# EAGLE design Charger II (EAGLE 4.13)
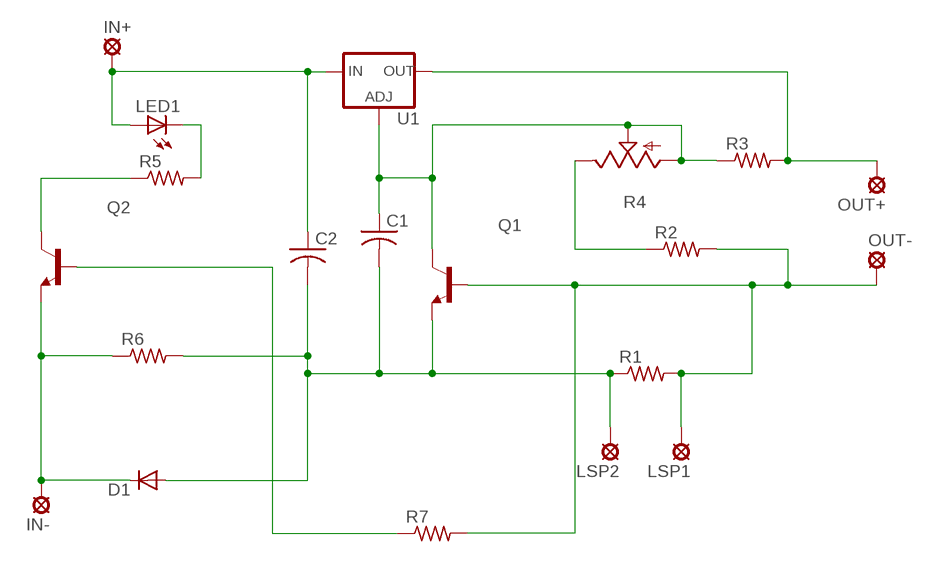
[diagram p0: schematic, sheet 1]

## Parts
C1  C-US050-024X044  [C050-024X044]
C2  C-US050-024X044  [C050-024X044]
D1  DIODE-C1702-05  [C1702-05]
IN+  SE14  [SE14]
IN-  SE14  [SE14]
LED1  LED3MM  [LED3MM]
LSP1  MCS08  [MCS08]
LSP2  MCS08  [MCS08]
OUT+  SE14  [SE14]
OUT-  SE14  [SE14]
Q1  2N3904  [TO92]
Q2  2N3904  [TO92]
R1  R-US_0207/2V  [0207/2V]
R2  R-US_0204/2V  [0204V]
R3  R-US_0204/2V  [0204V]
R4  TRIM_US-PTSPIN  [PT-SPIN]
R5  R-US_0207/2V  [0207/2V]
R6  R-US_0207/2V  [0207/2V]
R7  R-US_0309/V  [0309V]
U1  LM317TS  [317TS]

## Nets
N$1: C1.2 C2.2 D1.A LSP2.MP Q1.3(E) R1.1 R6.2
N$4: R2.1 R4.E
N$9: C1.1 Q1.1(C) R3.1 R4.A R4.S U1.1(ADJ)
N$10: LSP1.MP OUT-.MP Q1.2(B) R1.2 R2.2 R7.2
N$12: Q2.2(B) R7.1
N$13: LED1.K(C) R5.2
N$14: Q2.1(C) R5.1
N$15: OUT+.MP R3.2 U1.2(OUT)
N$17: C2.1 IN+.MP LED1.A U1.3(IN)
N$18: D1.C IN-.MP Q2.3(E) R6.1

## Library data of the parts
C1 C2 = rcl:C-US: CAPACITOR, American symbol
D1 = diode:DIODE-: DIODE
IN+ IN- OUT+ OUT- = solpad:SE14: SOLDER PAD
LED1 = led:LED: LED
LSP1 LSP2 = solpad:MCS08: SOLDER PAD
Q1 Q2 = 00 Dales Common:2N3904: NPN Transistor
R1-R3 R5-R7 = rcl:R-US_: RESISTOR, American symbol
R4 = pot:TRIM_US-: POTENTIOMETER
U1 = 00 Dales Common:LM317TS: VOLTAGE REGULATOR

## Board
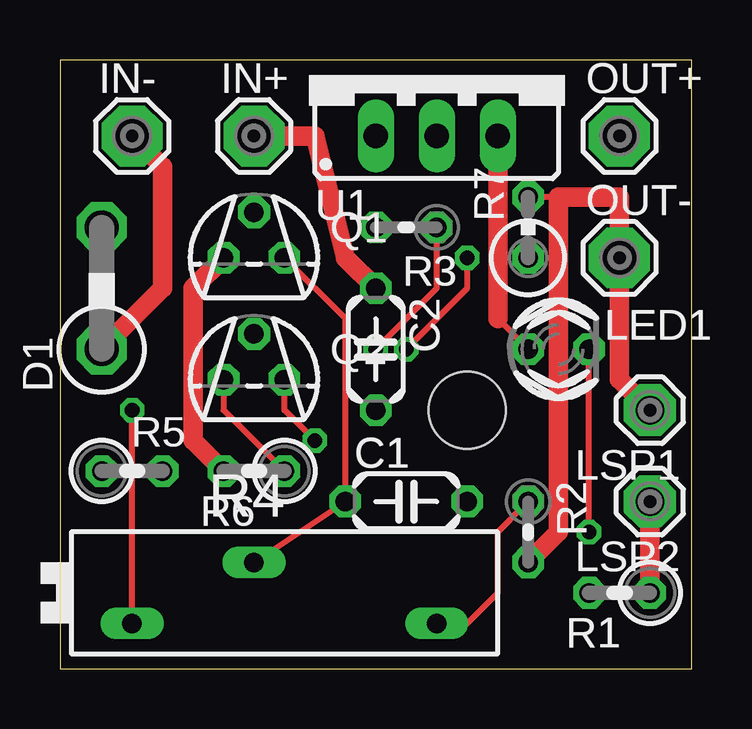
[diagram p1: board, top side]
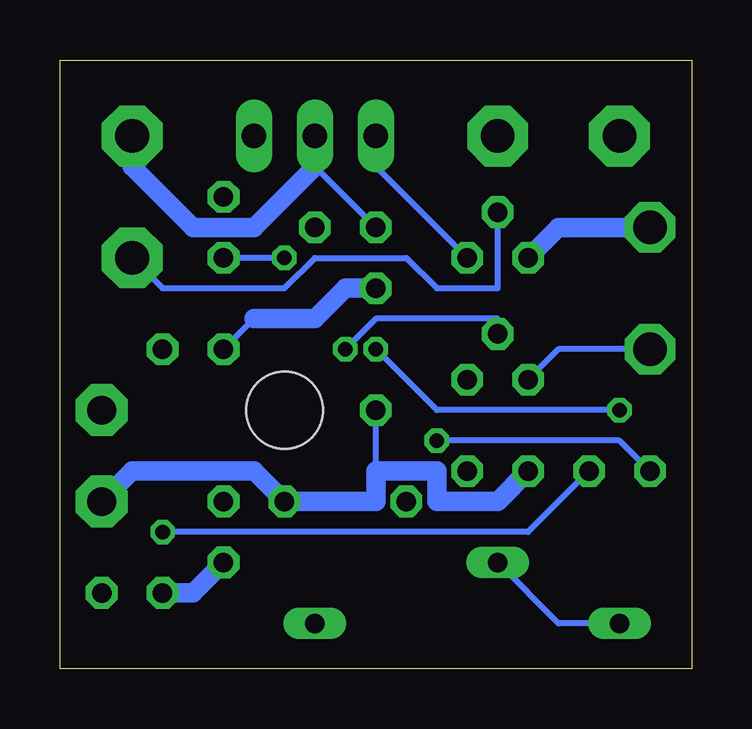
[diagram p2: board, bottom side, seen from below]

Size 26.34 x 25.39 mm. Coordinates in mm from the lower left corner, seen from the top.
Outline: 0,0 26.34,0 26.34,25.39 0,25.39 0,0
Copper layers (1*16): Top 0.035mm / dielectric 1.5mm / Bottom 0.035mm
Design rules "default": minimum track width 10mil, minimum drill 24mil, track to track 8mil, track to pad 8mil, pad to pad 8mil, via to via 8mil, smd to smd 8mil, copper to edge 40mil, drill to drill 8mil, minimum pad ring 10mil, minimum via ring 8mil, stop-mask expansion 4mil, vias tented up to drill 0mil, thermal gap 10mil
Holes 3.2 mm at 16.98,10.79

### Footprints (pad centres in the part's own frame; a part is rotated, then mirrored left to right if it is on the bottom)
C050-024X044 = drill 0.813 octagon: 1 -2.54,0; 2 2.54,0
C1702-05 = drill 1.397 octagon: A 2.54,0; C -2.54,0
SE14 = drill 1.397 pad 2.54 octagon: MP 0,0
LED3MM = drill 0.813 octagon: A -1.27,0; K 1.27,0
MCS08 = drill 1.194 pad 2.159 octagon: MP 0,0
TO92 = drill 0.813 octagon: 1 1.27,0; 2 0,1.905; 3 -1.27,0
0207/2V = drill 0.813 octagon: 1 -1.27,0; 2 1.27,0
0204V = drill 0.813 octagon: 1 -1.27,0; 2 1.27,0
PT-SPIN = drill 0.813 long: A -6.35,-1.27; E 6.35,-1.27; S -1.27,1.27
0309V = drill 0.813 octagon: 1 -1.27,0; 2 1.27,0
317TS = drill 1.016 long: 1 -2.54,-2.54; 2 0,-2.54; 3 2.54,-2.54

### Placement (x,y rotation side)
C1  14.44,6.98 0 top
C2  13.17,13.33 270 top
D1  1.74,15.87 90 top
IN+  8.09,22.22 0 top
IN-  3.01,22.22 0 top
LED1  20.79,13.33 0 top
LSP1  24.6,10.79 180 top
LSP2  24.6,6.98 180 top
OUT+  23.33,22.22 0 top
OUT-  23.33,17.14 0 top
Q1  8.09,17.14 0 top
Q2  8.09,12.06 0 top
R1  23.33,3.17 180 top
R2  19.52,5.71 270 top
R3  14.44,18.41 180 top
R4  9.36,3.17 0 top
R5  3.01,8.25 0 top
R6  8.09,8.25 180 top
R7  19.52,18.41 90 top
U1  15.71,24.76 0 top

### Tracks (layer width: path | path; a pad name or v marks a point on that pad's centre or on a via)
N$1
  Top 0.813: LSP2.MP R1.1 | Q1.3 5.55,15.87 5.55,9.52 R6.2
  Bottom 0.254: 13.17,8.25 C2.2
  Bottom 0.813: R6.2 8.09,6.98 10.63,6.98 10.63,8.25 13.17,8.25 13.17,6.98 C1.2 18.25,8.25 23.33,8.25 LSP2.MP | Q1.3 5.55,18.41 D1.A
N$4
  Top 0.254: R4.E 16.98,1.9 18.25,3.17 18.25,5.71 R2.1
N$9  (via drill 0.61)
  Top 0.254: R4.S C1.1 11.9,14.6 Q1.1 | R4.A v3.01,10.79 | v13.17,13.33 15.71,15.87 R3.1
  Bottom 0.254: Q1.1 13.17,20.95 U1.1 | v3.01,10.79 10.63,10.79 v13.17,13.33 | R4.S 5.55,1.9 R4.A
N$10
  Top 0.254: 20.79,19.68 R7.2
  Top 0.813: R2.2 20.79,5.71 20.79,19.68 23.33,19.68 OUT-.MP 23.33,12.06 LSP1.MP
  Bottom 0.254: OUT-.MP 22.06,15.87 16.98,15.87 15.71,17.14 11.9,17.14 10.63,15.87 8.09,15.87 Q1.2
  Bottom 0.813: R2.2 20.79,3.17 R1.2
N$12  (via drill 0.61)
  Top 0.254: v14.44,13.33 16.98,15.87 v16.98,17.14
  Bottom 0.254: v14.44,13.33 13.17,14.6 8.09,14.6 Q2.2 | v16.98,17.14 R7.1
N$13  (via drill 0.61)
  Top 0.254: v22.06,5.71 LED1.K
  Bottom 0.254: R5.2 6.82,5.71 v22.06,5.71
N$14  (via drill 0.61)
  Top 0.254: v10.63,9.52 9.36,10.79 Q2.1
  Bottom 0.254: R5.1 3.01,9.52 v10.63,9.52
N$15
  Bottom 0.254: R3.2 15.71,20.95
  Bottom 0.813: OUT+.MP 23.33,20.95 20.79,18.41 18.25,18.41 15.71,20.95 U1.2
N$17
  Top 0.254: LED1.A 18.25,14.6
  Top 0.813: 18.25,14.6 U1.3 | IN+.MP 10.63,22.22 11.9,17.14 C2.1
  Bottom 0.254: 18.25,14.6 LED1.A
  Bottom 0.813: 18.25,14.6 15.71,14.6 14.44,15.87 C2.1
N$18
  Top 0.254: R6.1 6.82,10.79 Q2.3
  Top 0.813: IN-.MP 4.28,20.95 4.28,15.87 D1.C
  Bottom 0.254: Q2.3 5.55,13.33 D1.C

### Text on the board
tNames: IN- | IN- | IN+ | IN+ | OUT+ | OUT+ | U1 | U1 | R7 | R7 | OUT- | OUT- | Q1 | Q1 | R3 | R3 | C2 | C2 | LED1 | LED1 | Q2 | Q2 | D1 | D1 | R5 | R5 | LSP1 | LSP1 | C1 | C1 | R6 | R6 | R2 | R2 | R4 | R4 | LSP2 | LSP2 | R1 | R1
tValues: SE14 | SE14 | SE14 | SE14 | SE14 | SE14 | SE14 | SE14 | MCS08 | MCS08 | MCS08 | MCS08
